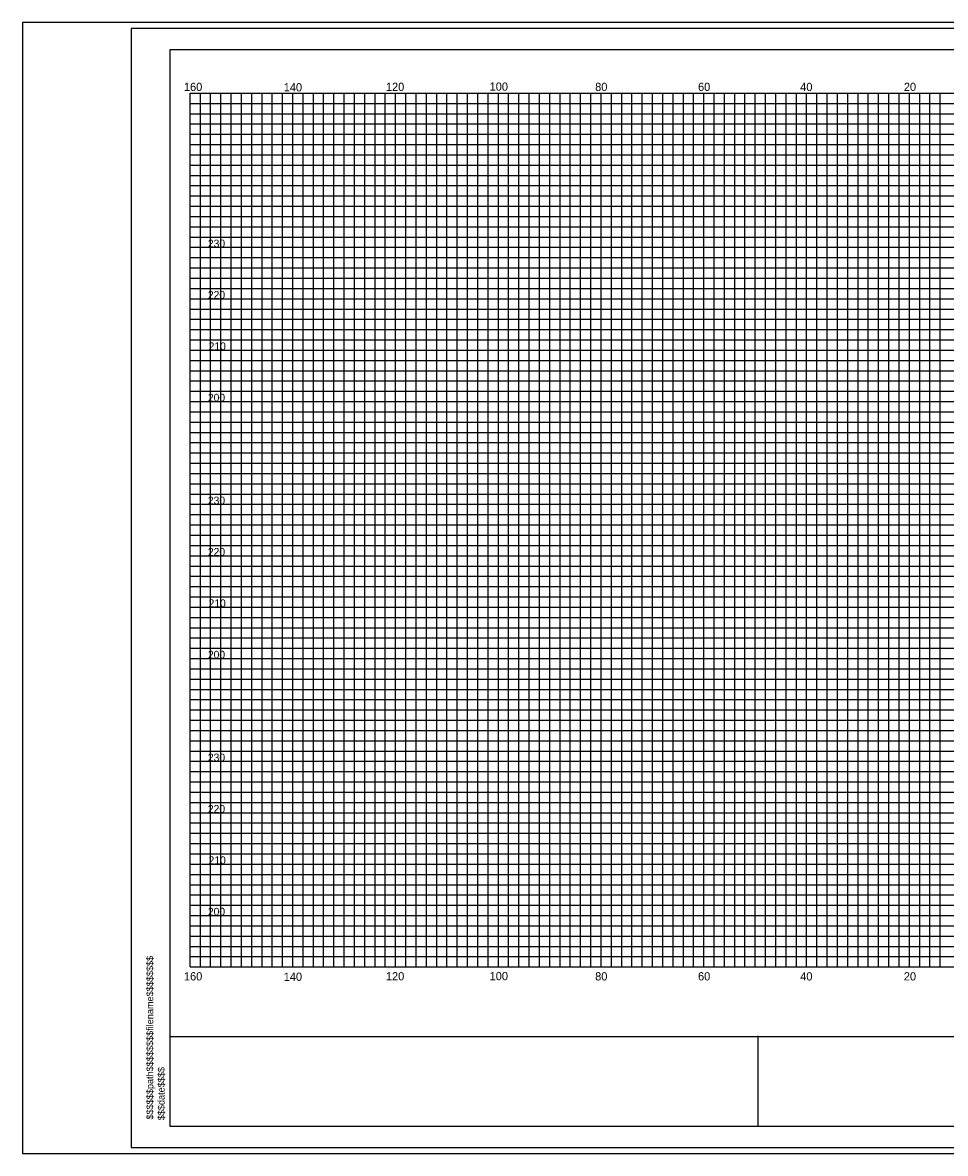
# Model space of a CAD drawing. Extents: x 967 to 1326, y 964 to 2304.
# Drawn here: x 967.4 to 1147, y 963.7 to 1183.7 of the extents above; entities that cross this region are included whole.
import ezdxf

# ---------------------------------------------------------------- set-up
doc = ezdxf.new("R2010")
doc.units = 0
for name, color, linetype in [('Default', 7, 'Continuous'), ('RD_GPK_XS_Cell', 7, 'Continuous'), ('RD_PD_PaveShd', 7, 'Continuous'), ('RD_XS_ExGround', 7, 'Continuous'), ('RD_XS_ExPaveRet', 7, 'Continuous'), ('RD_XS_PaveOvlay', 7, 'Continuous'), ('RD_XS_TX_Elev_EX', 7, 'Continuous')]:
    doc.layers.add(name, color=color, linetype=linetype)

msp = doc.modelspace()

# ---------------------------------------------------------------- linework, layer by layer
at = {"layer": 'RD_GPK_XS_Cell'}
for p, q in [((1000, 1170), (1320, 1170)), ((1000, 1000), (1000, 1170)), ((1010, 1000), (1010, 1170)), ((1020, 1000), (1020, 1170)), ((1030, 1000), (1030, 1170)), ((1040, 1000), (1040, 1170)), ((1050, 1000), (1050, 1170)), ((1060, 1000), (1060, 1170)), ((1070, 1000), (1070, 1170)), ((1080, 1000), (1080, 1170)), ((1090, 1000), (1090, 1170)), ((1100, 1000), (1100, 1170)), ((1110, 1000), (1110, 1170)), ((1120, 1000), (1120, 1170)), ((1130, 1000), (1130, 1170)), ((1140, 1000), (1140, 1170)), ((1000, 1160), (1320, 1160)), ((1000, 1150), (1320, 1150)), ((1000, 1140), (1320, 1140)), ((1000, 1130), (1320, 1130)), ((1000, 1120), (1320, 1120)), ((1000, 1110), (1320, 1110)), ((1000, 1100), (1320, 1100)), ((1000, 1090), (1320, 1090)), ((1000, 1080), (1320, 1080)), ((1000, 1070), (1320, 1070)), ((1000, 1060), (1320, 1060)), ((1000, 1050), (1320, 1050)), ((1000, 1040), (1320, 1040)), ((1000, 1030), (1320, 1030)), ((1000, 1020), (1320, 1020)), ((1000, 1010), (1320, 1010)), ((1000, 1000), (1320, 1000))]:
    msp.add_line(p, q, dxfattribs=at)
at = {"layer": 'RD_PD_PaveShd'}
for p, q in [((996.11, 968.98), (996.11, 1178.46)), ((996.11, 1178.46), (1323.89, 1178.46)), ((996.11, 986.49), (1323.89, 986.49)), ((1110.59, 968.98), (1110.59, 986.56)), ((1323.89, 968.98), (996.11, 968.98))]:
    msp.add_line(p, q, dxfattribs=at)
at = {"layer": 'RD_XS_ExGround'}
for p, q in [((1002, 1000), (1002, 1170)), ((1004, 1000), (1004, 1170)), ((1006, 1000), (1006, 1170)), ((1008, 1000), (1008, 1170)), ((1012, 1000), (1012, 1170)), ((1014, 1000), (1014, 1170)), ((1016, 1000), (1016, 1170)), ((1018, 1000), (1018, 1170)), ((1022, 1000), (1022, 1170)), ((1024, 1000), (1024, 1170)), ((1026, 1000), (1026, 1170)), ((1028, 1000), (1028, 1170)), ((1032, 1000), (1032, 1170)), ((1034, 1000), (1034, 1170)), ((1036, 1000), (1036, 1170)), ((1038, 1000), (1038, 1170)), ((1042, 1000), (1042, 1170)), ((1044, 1000), (1044, 1170)), ((1046, 1000), (1046, 1170)), ((1048, 1000), (1048, 1170)), ((1052, 1000), (1052, 1170)), ((1054, 1000), (1054, 1170)), ((1056, 1000), (1056, 1170)), ((1058, 1000), (1058, 1170)), ((1062, 1000), (1062, 1170)), ((1064, 1000), (1064, 1170)), ((1066, 1000), (1066, 1170)), ((1068, 1000), (1068, 1170)), ((1072, 1000), (1072, 1170)), ((1074, 1000), (1074, 1170)), ((1076, 1000), (1076, 1170)), ((1078, 1000), (1078, 1170)), ((1082, 1000), (1082, 1170)), ((1084, 1000), (1084, 1170)), ((1086, 1000), (1086, 1170)), ((1088, 1000), (1088, 1170)), ((1092, 1000), (1092, 1170)), ((1094, 1000), (1094, 1170)), ((1096, 1000), (1096, 1170)), ((1098, 1000), (1098, 1170)), ((1102, 1000), (1102, 1170)), ((1104, 1000), (1104, 1170)), ((1106, 1000), (1106, 1170)), ((1108, 1000), (1108, 1170)), ((1112, 1000), (1112, 1170)), ((1114, 1000), (1114, 1170)), ((1116, 1000), (1116, 1170)), ((1118, 1000), (1118, 1170)), ((1122, 1000), (1122, 1170)), ((1124, 1000), (1124, 1170)), ((1126, 1000), (1126, 1170)), ((1128, 1000), (1128, 1170)), ((1132, 1000), (1132, 1170)), ((1134, 1000), (1134, 1170)), ((1136, 1000), (1136, 1170)), ((1138, 1000), (1138, 1170)), ((1142, 1000), (1142, 1170)), ((1144, 1000), (1144, 1170)), ((1146, 1000), (1146, 1170)), ((1000, 1168), (1320, 1168)), ((1000, 1166), (1320, 1166)), ((1000, 1164), (1320, 1164)), ((1000, 1162), (1320, 1162)), ((1000, 1158), (1320, 1158)), ((1000, 1156), (1320, 1156)), ((1000, 1154), (1320, 1154)), ((1000, 1152), (1320, 1152)), ((1000, 1148), (1320, 1148)), ((1000, 1146), (1320, 1146)), ((1000, 1144), (1320, 1144)), ((1000, 1142), (1320, 1142)), ((1000, 1138), (1320, 1138)), ((1000, 1136), (1320, 1136)), ((1000, 1134), (1320, 1134)), ((1000, 1132), (1320, 1132)), ((1000, 1128), (1320, 1128)), ((1000, 1126), (1320, 1126)), ((1000, 1124), (1320, 1124)), ((1000, 1122), (1320, 1122)), ((1000, 1118), (1320, 1118)), ((1000, 1116), (1320, 1116)), ((1000, 1114), (1320, 1114)), ((1000, 1112), (1320, 1112)), ((1000, 1108), (1320, 1108)), ((1000, 1106), (1320, 1106)), ((1000, 1104), (1320, 1104)), ((1000, 1102), (1320, 1102)), ((1000, 1098), (1320, 1098)), ((1000, 1096), (1320, 1096)), ((1000, 1094), (1320, 1094)), ((1000, 1092), (1320, 1092)), ((1000, 1088), (1320, 1088)), ((1000, 1086), (1320, 1086)), ((1000, 1084), (1320, 1084)), ((1000, 1082), (1320, 1082)), ((1000, 1078), (1320, 1078)), ((1000, 1076), (1320, 1076)), ((1000, 1074), (1320, 1074)), ((1000, 1072), (1320, 1072)), ((1000, 1068), (1320, 1068)), ((1000, 1066), (1320, 1066)), ((1000, 1064), (1320, 1064)), ((1000, 1062), (1320, 1062)), ((1000, 1058), (1320, 1058)), ((1000, 1056), (1320, 1056)), ((1000, 1054), (1320, 1054)), ((1000, 1052), (1320, 1052)), ((1000, 1048), (1320, 1048)), ((1000, 1046), (1320, 1046)), ((1000, 1044), (1320, 1044)), ((1000, 1042), (1320, 1042)), ((1000, 1038), (1320, 1038)), ((1000, 1036), (1320, 1036)), ((1000, 1034), (1320, 1034)), ((1000, 1032), (1320, 1032)), ((1000, 1028), (1320, 1028)), ((1000, 1026), (1320, 1026)), ((1000, 1024), (1320, 1024)), ((1000, 1022), (1320, 1022)), ((1000, 1018), (1320, 1018)), ((1000, 1016), (1320, 1016)), ((1000, 1014), (1320, 1014)), ((1000, 1012), (1320, 1012)), ((1000, 1008), (1320, 1008)), ((1000, 1006), (1320, 1006)), ((1000, 1004), (1320, 1004)), ((1000, 1002), (1320, 1002))]:
    msp.add_line(p, q, dxfattribs=at)
at = {"layer": 'RD_XS_PaveOvlay'}
msp.add_lwpolyline([(967.41, 963.72), (1326.28, 963.72), (1326.28, 1183.72), (967.41, 1183.72)], close=True, dxfattribs=at)
at = {"layer": 'RD_XS_TX_Elev_EX'}
for points in [[(967.41, 963.72), (1326.28, 963.72), (1326.28, 1183.72), (967.41, 1183.72)], [(988.52, 964.84), (1326.28, 964.84), (1326.28, 1182.6), (988.52, 1182.6)]]:
    msp.add_lwpolyline(points, close=True, dxfattribs=at)

# ---------------------------------------------------------------- texts
at = {"layer": 'Default'}
for s, p in [('230', (1003.47, 1140)), ('220', (1003.47, 1130)), ('210', (1003.61, 1120)), ('200', (1003.47, 1110)), ('230', (1003.47, 1090)), ('220', (1003.47, 1080)), ('210', (1003.61, 1070)), ('200', (1003.47, 1060)), ('230', (1003.47, 1040)), ('220', (1003.47, 1030)), ('210', (1003.61, 1020)), ('200', (1003.47, 1010))]:
    msp.add_text(s, height=1.5, dxfattribs=at).set_placement(p)
for s, p in [('$$$$$$path$$$$$$$$filename$$$$$$$$', (992.83, 970.31)), ('$$$date$$$$', (995.04, 970.17))]:
    msp.add_text(s, height=1.3258, rotation=90, dxfattribs=at).set_placement(p)
at = {"layer": 'RD_XS_ExPaveRet'}
for s, p in [('160', (998.81, 1170.42)), ('140', (1018.23, 1170.34)), ('120', (1038.12, 1170.43)), ('100', (1058.3, 1170.47)), ('80', (1078.84, 1170.42)), ('60', (1098.86, 1170.42)), ('40', (1118.75, 1170.41)), ('20', (1138.91, 1170.42)), ('160', (998.81, 997.37)), ('140', (1018.23, 997.29)), ('120', (1038.12, 997.38)), ('100', (1058.3, 997.42)), ('80', (1078.84, 997.37)), ('60', (1098.86, 997.37)), ('40', (1118.75, 997.36)), ('20', (1138.91, 997.37))]:
    msp.add_text(s, height=1.6, dxfattribs=at).set_placement(p)

doc.saveas('drawing.dxf')
